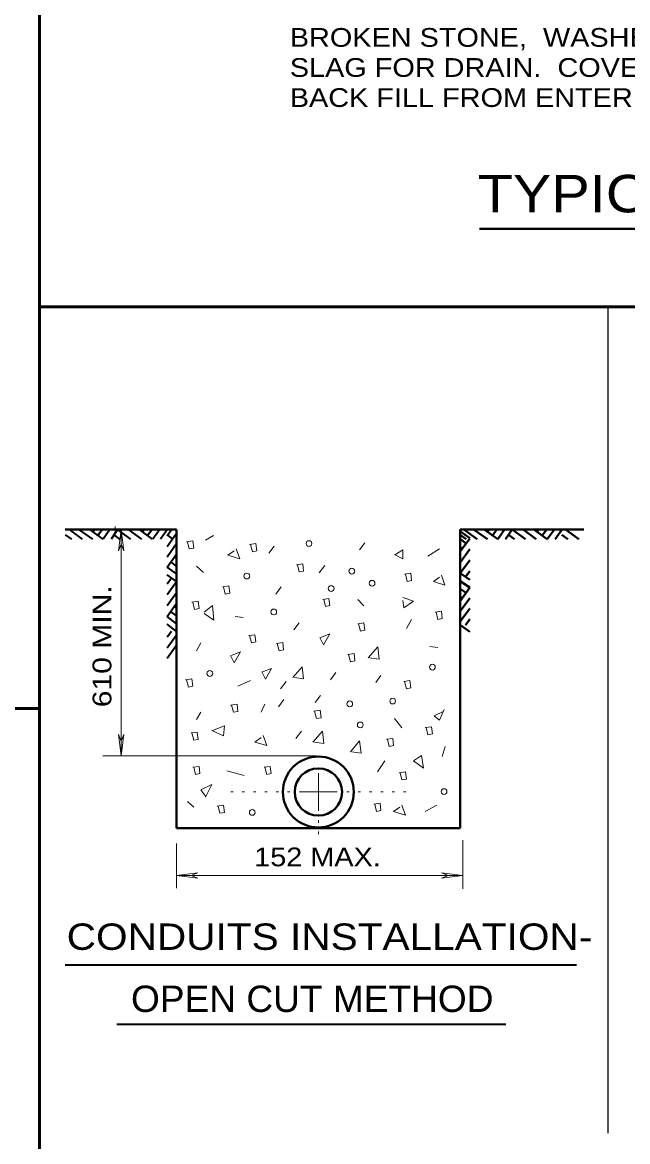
# Model space of a CAD drawing. Extents: x 312583 to 312854, y 144419 to 144597.
# Drawn here: x 312741.44 to 312765.96, y 144443.94 to 144489.34 of the extents above; entities that cross this region are included whole.
import ezdxf
from ezdxf.enums import TextEntityAlignment as Align

# ---------------------------------------------------------------- set-up
doc = ezdxf.new("R2010")
doc.units = 0
doc.header["$LTSCALE"] = 0.3
doc.linetypes.add('DOTTED', pattern=[1.5, 0.3, -1.2])
doc.layers.add('1', color=7, linetype='Continuous', lineweight=40)
doc.layers.add('2', color=7, linetype='Continuous', lineweight=13)

msp = doc.modelspace()

# ---------------------------------------------------------------- linework, layer by layer
at = {"layer": '1', "lineweight": 53}
for p, q in [((312742.1369, 144540.9979), (312742.1369, 144423.0846)), ((312796.6103, 144477.7945), (312742.1369, 144477.7945)), ((312742.1369, 144461.5065), (312616.5, 144461.5065))]:
    msp.add_line(p, q, dxfattribs=at)
at = {"layer": '1', "lineweight": 25}
msp.add_line((312765.1773, 144444.2829), (312765.1773, 144477.7945), dxfattribs=at)
at = {"layer": '1'}
for p, q in [((312747.6819, 144468.7626), (312743.1739, 144468.7626)), ((312747.6819, 144468.7626), (312747.6819, 144463.6029)), ((312759.1819, 144468.7626), (312764.1959, 144468.7626)), ((312759.1819, 144456.6569), (312759.1819, 144468.7626)), ((312759.1896, 144468.6859), (312759.5729, 144468.4176)), ((312759.8643, 144468.3792), (312759.3276, 144468.7626)), ((312760.2859, 144468.3792), (312759.7646, 144468.7472)), ((312760.6999, 144468.3792), (312760.1556, 144468.7702)), ((312760.3473, 144468.7626), (312760.2859, 144468.6782)), ((312760.6616, 144468.7626), (312760.4929, 144468.5249)), ((312760.9759, 144468.7626), (312760.6999, 144468.3792)), ((312761.2903, 144468.7626), (312761.0143, 144468.3792)), ((312761.8193, 144468.3792), (312761.2903, 144468.7626)), ((312762.2639, 144468.3792), (312761.7273, 144468.7626)), ((312762.7009, 144468.3792), (312762.1643, 144468.7626)), ((312762.3559, 144468.7549), (312762.2946, 144468.6706)), ((312762.6703, 144468.7549), (312762.5016, 144468.5249)), ((312762.9846, 144468.7549), (312762.7086, 144468.3716)), ((312763.2989, 144468.7549), (312763.0229, 144468.3716)), ((312763.9813, 144468.3792), (312763.4446, 144468.7626)), ((312759.4273, 144468.3792), (312759.1819, 144468.5556)), ((312759.5653, 144468.4022), (312759.1819, 144467.8732)), ((312759.1896, 144468.3716), (312759.4196, 144468.2029)), ((312761.3823, 144468.3792), (312761.1369, 144468.5556)), ((312763.5366, 144468.3792), (312763.2989, 144468.5556)), ((312759.5653, 144467.9652), (312759.1819, 144467.4286)), ((312759.1896, 144468.0572), (312759.2739, 144467.9959)), ((312759.5653, 144467.5282), (312759.1819, 144466.9916)), ((312759.1819, 144466.9916), (312759.5653, 144466.7232)), ((312759.5653, 144467.0836), (312759.3889, 144466.8459)), ((312759.5653, 144466.4089), (312759.1743, 144465.8646)), ((312759.1819, 144466.6772), (312759.5653, 144466.4089)), ((312759.1819, 144466.3629), (312759.4196, 144466.1942)), ((312759.1819, 144466.0486), (312759.2663, 144465.9872)), ((312759.5653, 144465.9872), (312759.1973, 144465.4659)), ((312759.5653, 144465.5656), (312759.1819, 144465.0366)), ((312759.5653, 144465.1286), (312759.3889, 144464.8832)), ((312759.1896, 144464.8832), (312759.5729, 144464.6149)), ((312747.6819, 144456.6569), (312759.1819, 144456.6569))]:
    msp.add_line(p, q, dxfattribs=at)
at = {"layer": '2', "lineweight": 40}
for p, q in [((312759.9676, 144480.9679), (312783.709, 144480.9679)), ((312744.3546, 144468.7626), (312744.2933, 144468.6782)), ((312744.6689, 144468.7626), (312744.5003, 144468.5249)), ((312746.3633, 144468.7549), (312746.3019, 144468.6706)), ((312746.6776, 144468.7549), (312746.5089, 144468.5249)), ((312747.6819, 144463.6029), (312747.6819, 144456.6569))]:
    msp.add_line(p, q, dxfattribs=at)
at = {"layer": '2', "lineweight": 35}
for p, q in [((312743.8716, 144468.3792), (312743.3426, 144468.7626)), ((312744.2933, 144468.3792), (312743.7719, 144468.7472)), ((312744.7149, 144468.3792), (312744.1706, 144468.7702)), ((312744.9833, 144468.7626), (312744.7149, 144468.3792)), ((312745.2976, 144468.7626), (312745.0293, 144468.3792)), ((312745.8343, 144468.3792), (312745.2976, 144468.7626)), ((312746.2713, 144468.3792), (312745.7346, 144468.7626)), ((312746.7083, 144468.3792), (312746.1793, 144468.7626)), ((312746.9919, 144468.7549), (312746.7236, 144468.3716)), ((312747.3063, 144468.7549), (312747.0303, 144468.3716)), ((312747.2986, 144468.5172), (312747.4749, 144468.7626)), ((312743.4346, 144468.3792), (312743.1893, 144468.5556)), ((312745.3896, 144468.3792), (312745.1519, 144468.5556)), ((312747.2986, 144468.0802), (312747.6819, 144468.6169)), ((312747.5439, 144468.3792), (312747.3063, 144468.5556)), ((312747.2986, 144467.6586), (312747.6743, 144468.1799)), ((312747.2986, 144467.2446), (312747.6896, 144467.7889)), ((312747.6819, 144467.2829), (312747.4519, 144467.4516)), ((312747.6819, 144467.5972), (312747.5976, 144467.6586)), ((312747.6819, 144466.9686), (312747.2986, 144467.2446)), ((312747.6819, 144466.6542), (312747.2986, 144466.9302)), ((312747.2986, 144466.5622), (312747.4749, 144466.8076)), ((312747.2986, 144466.1252), (312747.6819, 144466.6542)), ((312747.2986, 144465.6806), (312747.6819, 144466.2172)), ((312747.2986, 144465.2436), (312747.6819, 144465.7802)), ((312747.6743, 144465.5886), (312747.5899, 144465.6499)), ((312747.6743, 144464.9599), (312747.2986, 144465.2359)), ((312747.6743, 144465.2742), (312747.4443, 144465.4429)), ((312747.6743, 144464.6456), (312747.2986, 144464.9216)), ((312747.2986, 144464.4079), (312747.4749, 144464.6456)), ((312747.2986, 144463.9632), (312747.6819, 144464.4999)), ((312747.2986, 144463.5416), (312747.6743, 144464.0629)), ((312743.1663, 144451.1138), (312763.8969, 144451.1138)), ((312745.2669, 144448.7023), (312761.024, 144448.7023))]:
    msp.add_line(p, q, dxfattribs=at)
at = {"layer": '2'}
for p, q in [((312745.1979, 144468.4636), (312745.1979, 144468.8929)), ((312745.4433, 144468.7626), (312745.3359, 144467.8962)), ((312745.4433, 144459.5856), (312745.4433, 144468.7626)), ((312745.4433, 144468.7626), (312745.5506, 144467.8962)), ((312748.8549, 144468.3409), (312749.1846, 144468.5249)), ((312755.3179, 144468.2336), (312755.0956, 144467.9422)), ((312745.3359, 144467.8962), (312745.4433, 144468.1722)), ((312745.5506, 144467.8962), (312745.4433, 144468.1722)), ((312751.6456, 144468.0956), (312751.4233, 144467.8042)), ((312757.8709, 144467.6816), (312758.3463, 144467.9806)), ((312748.4869, 144467.2829), (312748.7783, 144467.0222)), ((312753.6926, 144467.3059), (312753.4703, 144467.0146)), ((312751.9293, 144466.4396), (312751.7069, 144466.1482)), ((312755.0266, 144465.9259), (312755.2796, 144465.6729)), ((312750.0586, 144465.2359), (312750.3883, 144465.1976)), ((312757.2116, 144465.1209), (312756.9969, 144464.7529)), ((312752.6576, 144464.9829), (312752.4353, 144464.6916)), ((312748.4869, 144463.8406), (312748.6709, 144464.1702)), ((312757.9476, 144464.0246), (312758.2696, 144463.9862)), ((312754.1373, 144462.9666), (312753.9226, 144462.6752)), ((312755.7549, 144462.5602), (312755.9696, 144462.8516)), ((312750.1659, 144462.4146), (312750.6796, 144462.6369)), ((312752.1209, 144462.5986), (312751.8986, 144462.3072)), ((312752.0366, 144461.8702), (312751.8219, 144461.5789)), ((312753.5239, 144462.0389), (312753.3016, 144461.7476)), ((312751.2623, 144461.6862), (312751.1166, 144461.3566)), ((312748.6709, 144461.3566), (312748.4869, 144461.0576)), ((312756.5216, 144461.0959), (312756.8129, 144460.7279)), ((312752.7419, 144460.5822), (312752.5196, 144460.2909)), ((312745.3359, 144460.4519), (312745.4433, 144460.1759)), ((312745.4433, 144459.5856), (312745.3359, 144460.4519)), ((312745.5506, 144460.4519), (312745.4433, 144460.1759)), ((312745.4433, 144459.5856), (312745.5506, 144460.4519)), ((312753.3553, 144459.5856), (312744.6919, 144459.5856)), ((312758.5686, 144459.9612), (312758.4536, 144459.5626)), ((312756.1229, 144459.3786), (312755.8239, 144458.9416)), ((312750.4266, 144458.7882), (312749.7289, 144458.9722)), ((312753.4319, 144458.1212), (312753.4319, 144458.8879)), ((312753.4319, 144458.1212), (312752.6653, 144458.1212)), ((312753.4319, 144458.1212), (312754.1986, 144458.1212)), ((312753.4319, 144458.1212), (312753.4319, 144457.3546)), ((312748.1266, 144457.7302), (312748.3796, 144457.5079)), ((312757.7636, 144457.3316), (312758.2389, 144457.5846)), ((312747.6819, 144456.0286), (312747.6819, 144454.22)), ((312759.2893, 144456.1704), (312759.2893, 144454.1846)), ((312747.6819, 144454.7334), (312748.5483, 144454.8408)), ((312747.6819, 144454.7334), (312759.2893, 144454.7334)), ((312747.6819, 144454.7334), (312748.5483, 144454.6261)), ((312748.5483, 144454.8408), (312748.2723, 144454.7334)), ((312748.5483, 144454.6261), (312748.2723, 144454.7334)), ((312758.4229, 144454.8408), (312758.6989, 144454.7334)), ((312759.2893, 144454.7334), (312758.4229, 144454.8408)), ((312758.4229, 144454.6261), (312758.6989, 144454.7334)), ((312759.2893, 144454.7334), (312758.4229, 144454.6261))]:
    msp.add_line(p, q, dxfattribs=at)
at = {"layer": '2', "linetype": 'DOTTED'}
for p, q in [((312752.2819, 144458.1212), (312749.6369, 144458.1212)), ((312754.5819, 144458.1212), (312757.3266, 144458.1212)), ((312753.4319, 144456.9712), (312753.4319, 144456.2046))]:
    msp.add_line(p, q, dxfattribs=at)
at = {"layer": '2'}
for points in [[(312748.0883, 144468.2719), (312748.3413, 144468.3102), (312748.3796, 144468.0112), (312748.1956, 144467.9806), (312748.1266, 144468.2719)], [(312750.6413, 144468.1646), (312750.9019, 144468.1952), (312750.9326, 144467.9039), (312750.7563, 144467.8656), (312750.6796, 144468.1646)], [(312750.0203, 144467.9039), (312749.7673, 144467.7199), (312750.2426, 144467.5742), (312750.0969, 144467.9806)], [(312756.5599, 144467.7582), (312756.8513, 144467.9422), (312756.8513, 144467.5742), (312756.5216, 144467.7582)], [(312752.5426, 144467.3366), (312752.8033, 144467.3749), (312752.8339, 144467.0759), (312752.6576, 144467.0452), (312752.5809, 144467.3366)], [(312756.9203, 144466.9532), (312757.1809, 144466.9916), (312757.2116, 144466.7002), (312757.0353, 144466.6619), (312756.9586, 144466.9532)], [(312758.3463, 144466.8382), (312758.0933, 144466.6619), (312758.5609, 144466.5162), (312758.4153, 144466.9149)], [(312749.5526, 144466.4396), (312749.8056, 144466.4779), (312749.8439, 144466.1866), (312749.6599, 144466.1482), (312749.5833, 144466.4396)], [(312753.6083, 144465.9336), (312753.8613, 144465.9719), (312753.8996, 144465.6806), (312753.7156, 144465.6422), (312753.6466, 144465.9336)], [(312756.8513, 144465.8876), (312756.8896, 144465.5962), (312757.2883, 144465.8569), (312756.8513, 144466.0026)], [(312748.3106, 144465.8186), (312748.5636, 144465.8569), (312748.6019, 144465.5656), (312748.4179, 144465.5272), (312748.3413, 144465.8186)], [(312748.8089, 144465.4122), (312749.1386, 144465.6882), (312749.1923, 144465.0902), (312748.8089, 144465.3586)], [(312758.1623, 144465.4199), (312758.4229, 144465.4506), (312758.4536, 144465.1592), (312758.2773, 144465.1209), (312758.2006, 144465.4199)], [(312755.0266, 144464.9369), (312755.2796, 144464.9752), (312755.3179, 144464.6839), (312755.1339, 144464.6456), (312755.0649, 144464.9369)], [(312750.6106, 144464.4616), (312750.8636, 144464.4999), (312750.9019, 144464.2086), (312750.7179, 144464.1702), (312750.6413, 144464.4616)], [(312751.7299, 144464.1396), (312751.9906, 144464.1779), (312752.0213, 144463.8866), (312751.8449, 144463.8482), (312751.7683, 144464.1396)], [(312753.5239, 144464.3849), (312753.8919, 144464.5306), (312753.6389, 144464.0936), (312753.4933, 144464.3849)], [(312749.9129, 144463.6566), (312750.2809, 144463.8022), (312750.0203, 144463.3652), (312749.8746, 144463.6566)], [(312754.6203, 144463.6949), (312754.8809, 144463.7332), (312754.9116, 144463.4419), (312754.7353, 144463.4036), (312754.6586, 144463.6949)], [(312755.4559, 144463.5646), (312755.8393, 144464.0016), (312755.8929, 144463.5109), (312755.5096, 144463.5646)], [(312752.3969, 144462.7596), (312752.7803, 144463.1966), (312752.8339, 144462.7059), (312752.4583, 144462.7596)], [(312751.1703, 144462.9896), (312751.5383, 144463.1352), (312751.2853, 144462.6906), (312751.1396, 144462.9896)], [(312748.0499, 144462.6752), (312748.3106, 144462.7059), (312748.3413, 144462.4146), (312748.1649, 144462.3762), (312748.0883, 144462.6752)], [(312756.8896, 144462.5986), (312757.1426, 144462.6369), (312757.1809, 144462.3456), (312756.9969, 144462.3072), (312756.9203, 144462.5986)], [(312749.8746, 144461.6479), (312750.1353, 144461.6862), (312750.1659, 144461.3872), (312749.9896, 144461.3566), (312749.9129, 144461.6479)], [(312753.2479, 144461.3949), (312753.5009, 144461.4332), (312753.5393, 144461.1342), (312753.3553, 144461.1036), (312753.2786, 144461.3949)], [(312758.4919, 144461.3872), (312758.1239, 144461.2032), (312758.3463, 144461.0269), (312758.5303, 144461.4639)], [(312748.2723, 144460.5132), (312748.5253, 144460.5516), (312748.5636, 144460.2526), (312748.3796, 144460.2219), (312748.3106, 144460.5132)], [(312749.1463, 144460.6206), (312749.6216, 144460.8046), (312749.5833, 144460.3982), (312749.1079, 144460.6206)], [(312753.2096, 144460.1452), (312753.5929, 144460.5822), (312753.6466, 144460.0916), (312753.2709, 144460.1452)], [(312757.7636, 144460.7356), (312758.0166, 144460.7662), (312758.0549, 144460.4749), (312757.8709, 144460.4366), (312757.8019, 144460.7356)], [(312751.1166, 144460.3292), (312750.8636, 144460.1452), (312751.3389, 144459.9996), (312751.1933, 144460.4059)], [(312754.7276, 144459.7542), (312755.1033, 144460.1912), (312755.1646, 144459.7006), (312754.7813, 144459.7542)], [(312756.1919, 144460.2602), (312756.4449, 144460.2909), (312756.4833, 144459.9996), (312756.2993, 144459.9612), (312756.2303, 144460.2602)], [(312748.3413, 144459.1256), (312748.6019, 144459.1562), (312748.6326, 144458.8649), (312748.4563, 144458.8266), (312748.3796, 144459.1256)], [(312751.2316, 144459.1256), (312751.4846, 144459.1562), (312751.5229, 144458.8649), (312751.3389, 144458.8266), (312751.2623, 144459.1256)], [(312756.7056, 144458.9032), (312756.9586, 144458.9416), (312756.9969, 144458.6426), (312756.8129, 144458.6119), (312756.7439, 144458.9032)], [(312748.8549, 144457.9142), (312749.1079, 144458.4279), (312748.6709, 144458.2056), (312748.8549, 144457.9526)], [(312749.3303, 144457.5462), (312749.5833, 144457.5846), (312749.6216, 144457.2932), (312749.4376, 144457.2549), (312749.3686, 144457.5462)], [(312755.6783, 144457.6229), (312755.9389, 144457.6612), (312755.9696, 144457.3622), (312755.7933, 144457.3316), (312755.7166, 144457.6229)], [(312756.7363, 144457.5079), (312756.4833, 144457.3316), (312756.9586, 144457.1859), (312756.8129, 144457.5846)]]:
    msp.add_lwpolyline(points, dxfattribs=at)
msp.add_lwpolyline([(312757.2883, 144459.3786), (312757.6179, 144459.5932), (312757.6869, 144459.0872)], close=True, dxfattribs=at)
for centre in [(312753.0524, 144468.1972), (312750.532, 144466.8804), (312754.7889, 144467.0759), (312753.9494, 144466.3763), (312755.6074, 144466.5872), (312751.6245, 144465.4218), (312758.053, 144463.1831), (312749.0351, 144462.9282), (312756.443, 144461.807), (312754.7046, 144461.6939), (312755.132, 144460.841), (312758.5264, 144458.1347), (312750.7524, 144457.2913)]:
    msp.add_circle(centre, 0.117, dxfattribs=at)
at = {"layer": '2', "lineweight": 40}
for radius in [1.4375, 0.9583]:
    msp.add_circle((312753.4319, 144458.1193), radius, dxfattribs=at)

# ---------------------------------------------------------------- texts
at = {"layer": '2', "width": 1.15}
for s, p in [('BROKEN STONE,  WASHED GRAVEL OR BLAST FURNACE', (312752.2745, 144488.3489)), ('SLAG FOR DRAIN.  COVER WITH TAR PAPER TO PREVENT', (312752.2745, 144487.1289)), ('BACK FILL FROM ENTERING DRAIN.', (312752.2745, 144485.9089)), ('152 MAX.', (312750.8307, 144455.1064))]:
    msp.add_text(s, height=0.76, dxfattribs=at).set_placement(p)
at = {"layer": '2'}
for s, height, width, p in [('TYPICAL TEE DRAIN', 1.52, 1.15, (312771.3153, 144481.633)), ('CONDUITS INSTALLATION-', 1.07, 1.15, (312753.8832, 144451.7156)), ('OPEN CUT METHOD', 1.07, 1.05, (312753.1836, 144449.1951))]:
    msp.add_text(s, height=height, dxfattribs=dict(at, width=width)).set_placement(p, align=Align.CENTER)
at = {"layer": '2', "width": 1.2}
msp.add_text('610 MIN.', height=0.76, rotation=90, dxfattribs=at).set_placement((312745.0429, 144461.5569))

doc.saveas('drawing.dxf')
